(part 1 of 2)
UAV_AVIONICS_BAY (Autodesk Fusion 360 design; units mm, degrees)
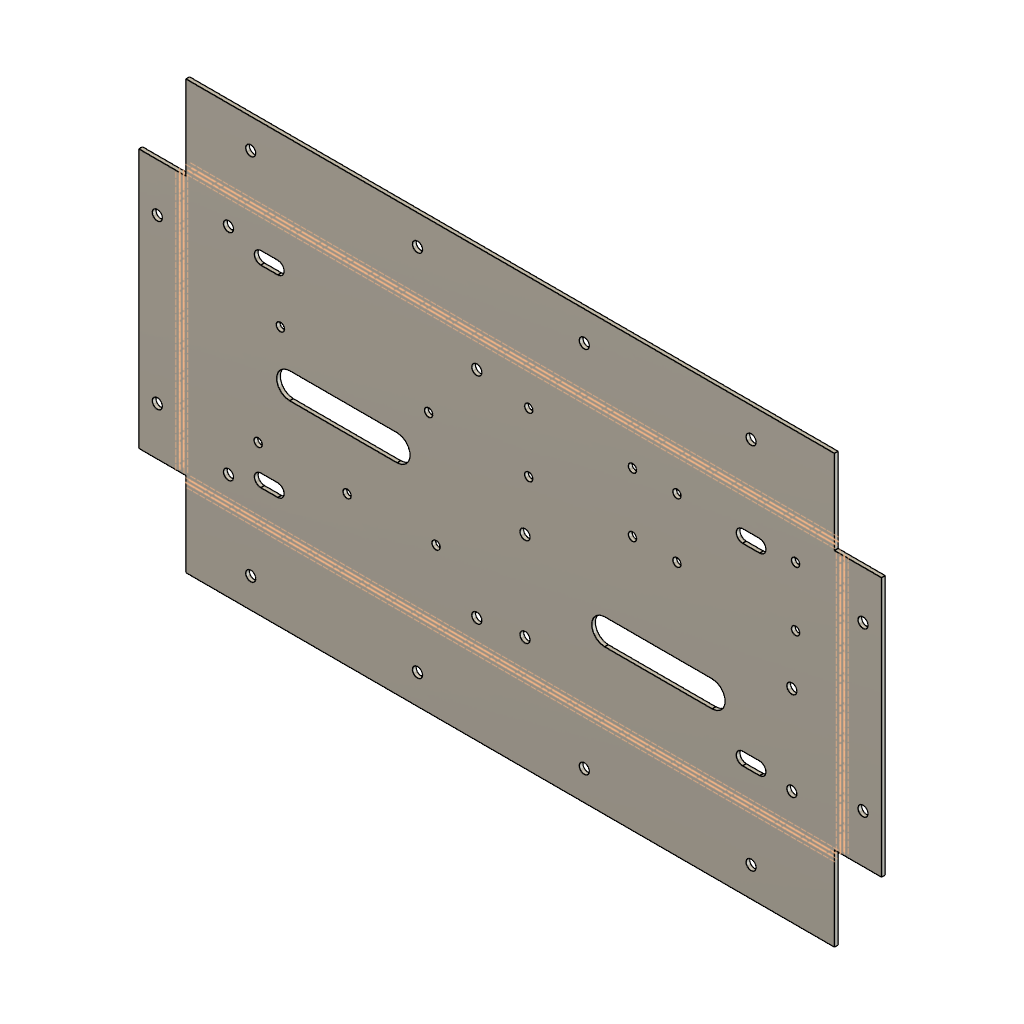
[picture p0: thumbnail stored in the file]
part number: 2026-11-24-01-47-07-089
part number: 2026-11-24-01-47-07-310
part number: 2026-11-24-01-47-07-319
part number: 2026-11-24-01-47-07-329
part number: 2026-11-24-01-47-07-338
part number: 2026-11-24-01-47-07-347
part number: 2026-11-24-01-47-07-356
part number: 2026-11-24-01-47-07-365
part number: 2026-11-24-01-47-07-376
part number: 2026-11-24-01-47-07-425
part number: 2026-11-24-01-47-08-424
part number: 2026-11-24-01-47-08-869
part number: 2026-11-24-01-47-09-436
part number: 2026-11-24-01-47-10-412
part number: 2026-11-24-01-47-11-202
part number: 2026-11-24-01-47-12-345
part number: 2026-11-24-01-47-13-053
part number: 2026-11-24-01-47-13-521
part number: 2026-11-24-01-47-15-030
part number: 2026-11-24-01-47-16-670
parameter "BAY_LENGTH" = 180 comment "[Assumption] Concept avionics bay overall outer length (X)"
parameter "BAY_WIDTH" = 75 comment "[Assumption] Concept avionics bay overall outer width (Y)"
parameter "BAY_HEIGHT" = 45 comment "[Assumption] Concept avionics bay overall outer height (Z)"
parameter "TRAY_FLANGE_H" = 22 comment "[Preliminary] Base tray perimeter upward flange height"
parameter "COVER_SKIRT_H" = 10 comment "[Preliminary] Top cover downward perimeter skirt height"
parameter "FORWARD_ZONE_END_X" = 94 comment "[Preliminary] X-boundary separating battery zone and aft deck"
parameter "HATCH_LENGTH" = 84 comment "[Preliminary] Service access hatch opening length"
parameter "HATCH_WIDTH" = 49 comment "[Preliminary] Service access hatch opening width"
parameter "T_BASE_TRAY" = 1 comment "[Preliminary] Main folded base tray thickness"
parameter "T_TOP_COVER" = 0.8 comment "[Preliminary] Removable top cover thickness"
parameter "T_ACCESS_HATCH" = 0.8 comment "[Preliminary] Service access hatch thickness"
parameter "T_SIDE_RAIL" = 1 comment "[Preliminary] Left and right side support rails thickness"
parameter "T_BULKHEAD" = 1 comment "[Preliminary] Front, rear, and connector bulkheads thickness"
parameter "T_EQUIP_DECK" = 1 comment "[Preliminary] Removable internal equipment deck thickness"
parameter "T_BRACKET" = 1 comment "[Preliminary] Structural and retention brackets thickness"
parameter "T_CABLE_CH" = 0.8 comment "[Preliminary] Cable routing channel and clamp thickness"
parameter "BEND_R_1_0" = 1 comment "[Preliminary] Inside bend radius for 1.0 mm Al 5052-H32"
parameter "BEND_R_0_8" = 0.8 comment "[Preliminary] Inside bend radius for 0.8 mm Al 5052-H32"
parameter "RELIEF_W_1_0" = 1.5 comment "[Preliminary] Bend relief width for 1.0 mm sheet"
parameter "RELIEF_D_1_0" = 2.5 comment "[Preliminary] Bend relief depth for 1.0 mm sheet"
parameter "RELIEF_W_0_8" = 1.2 comment "[Preliminary] Bend relief width for 0.8 mm sheet"
parameter "RELIEF_D_0_8" = 2.1 comment "[Preliminary] Bend relief depth for 0.8 mm sheet"
parameter "HOLE_CLR_M2_0" = 2.2 comment "[Preliminary] M2.0 medium clearance hole diameter"
parameter "HOLE_CLR_M2_5" = 2.7 comment "[Preliminary] M2.5 medium clearance hole diameter"
parameter "HOLE_CLR_M3_0" = 3.4 comment "[Preliminary] M3.0 medium clearance hole diameter"
parameter "HEAD_DIA_M2_0" = 3.8 comment "[Preliminary] ISO 4762/7380 M2.0 head diameter"
parameter "HEAD_DIA_M2_5" = 4.5 comment "[Preliminary] ISO 4762/7380 M2.5 head diameter"
parameter "STANDOFF_DECK_H" = 6 comment "[Preliminary] Under-deck plenum standoff height"
parameter "STANDOFF_PCB_H" = 4 comment "[Preliminary] PCB mounting standoff height"
parameter "ISO_PAD_THICK" = 2 comment "[Preliminary] Battery elastomer isolation pad thickness"
parameter "CLR_EQUIP_WALL" = 2 comment "[Preliminary] Minimum clearance between electronics and walls"
parameter "CLR_COMPONENT" = 1.5 comment "[Preliminary] General minimum clearance between adjacent parts"
parameter "CLR_SLIP_FIT" = 0.25 comment "[Preliminary] Per-side slip clearance for nested sheet metal parts"
parameter "CLR_COVER_FIT" = 0.3 comment "[Preliminary] Per-side clearance between cover skirt and chassis"
parameter "CLR_HATCH_GAP" = 0.5 comment "[Preliminary] Perimeter gap around removable service hatch"
parameter "d37" = 2
parameter "d38" = 1
parameter "d39" = 0.8
place_component sketch "SK_PCB_Substrate"
place_component sketch "SK_PCB_Substrate"
place_component sketch "SK_PCB_Substrate"
place_component sketch "SK_PCB_Substrate"
place_component sketch "SK_PCB_Substrate"
place_component sketch "SK_PCB_Substrate"
place_component sketch "SK_PCB_Substrate"
place_component sketch "SK_PCB_Substrate"
place_component sketch "SK_PCB_Substrate"
sketch "SK_Base_Tray_Blank" plane through (0, 0, 0) normal (0, 0, 1) x axis (1, 0, 0)
  line L1 (177.5, -37.5) -> (2.5, -37.5)
  line L2 (177.5, -35) -> (177.5, -37.5)
  line L3 (180, -35) -> (177.5, -35)
  line L4 (180, 35) -> (180, -35)
  line L5 (177.5, 35) -> (180, 35)
  line L6 (177.5, 37.5) -> (177.5, 35)
  line L7 (2.5, 37.5) -> (177.5, 37.5)
  line L8 (2.5, 35) -> (2.5, 37.5)
  line L9 (0, 35) -> (2.5, 35)
  line L10 (0, -35) -> (0, 35)
  line L11 (2.5, -35) -> (0, -35)
  line L12 (2.5, -37.5) -> (2.5, -35)
face "BaseFlange1" sketch "SK_Base_Tray_Blank"
face "EdgeFlange2" FlangeHeight 22 FlangeAngle 90
face "EdgeFlange3" FlangeHeight 12 FlangeAngle 90
sketch "SK_Base_Tray_Floor_Cutouts" plane through (0, 0, 0) normal (0, 0, 1) x axis (1, 0, 0)
  line L1 (27.3, -24.3) -> (22.7, -24.3)
  line L2 (22.7, -27.7) -> (27.3, -27.7)
  line L3 (27.3, 27.7) -> (22.7, 27.7)
  line L4 (22.7, 24.3) -> (27.3, 24.3)
  line L5 (157.3, -24.3) -> (152.7, -24.3)
  line L6 (152.7, -27.7) -> (157.3, -27.7)
  line L7 (157.3, 27.7) -> (152.7, 27.7)
  line L8 (152.7, 24.3) -> (157.3, 24.3)
  line L9 (64.5, -11.5) -> (35.5, -11.5)
  line L10 (35.5, -18.5) -> (64.5, -18.5)
  line L11 (149.5, 3.5) -> (120.5, 3.5)
  line L12 (120.5, -3.5) -> (149.5, -3.5)
  arc A1 centre (27.3, -26) radius 1.7 clockwise from (27.3, -24.3) to (27.3, -27.7)
  arc A2 centre (22.7, -26) radius 1.7 clockwise from (22.7, -27.7) to (22.7, -24.3)
  arc A3 centre (27.3, 26) radius 1.7 clockwise from (27.3, 27.7) to (27.3, 24.3)
  arc A4 centre (22.7, 26) radius 1.7 clockwise from (22.7, 24.3) to (22.7, 27.7)
  arc A5 centre (157.3, -26) radius 1.7 clockwise from (157.3, -24.3) to (157.3, -27.7)
  arc A6 centre (152.7, -26) radius 1.7 clockwise from (152.7, -27.7) to (152.7, -24.3)
  arc A7 centre (157.3, 26) radius 1.7 clockwise from (157.3, 27.7) to (157.3, 24.3)
  arc A8 centre (152.7, 26) radius 1.7 clockwise from (152.7, 24.3) to (152.7, 27.7)
  circle C1 centre (99, -29) radius 1.35
  circle C2 centre (99, 29) radius 1.35
  circle C3 centre (166, -29) radius 1.35
  circle C4 centre (166, 29) radius 1.35
  circle C5 centre (14, -27) radius 1.35
  circle C6 centre (14, -3) radius 1.35
  circle C7 centre (86, -27) radius 1.35
  circle C8 centre (86, -3) radius 1.35
  circle C9 centre (112, 12.5) radius 1.1
  circle C10 centre (152, 12.5) radius 1.1
  circle C11 centre (110, -17.5) radius 1.1
  circle C12 centre (134, -17.5) radius 1.1
  circle C13 centre (158, -17.5) radius 1.1
  circle C14 centre (13, 11) radius 1.1
  circle C15 centre (13, 27) radius 1.1
  circle C16 centre (45, 11) radius 1.1
  circle C17 centre (45, 27) radius 1.1
  circle C18 centre (57, 11) radius 1.1
  circle C19 centre (57, 27) radius 1.1
  circle C20 centre (85, 11) radius 1.1
  circle C21 centre (85, 27) radius 1.1
  arc A9 centre (64.5, -15) radius 3.5 clockwise from (64.5, -11.5) to (64.5, -18.5)
  arc A10 centre (35.5, -15) radius 3.5 clockwise from (35.5, -18.5) to (35.5, -11.5)
  arc A11 centre (149.5, 0) radius 3.5 clockwise from (149.5, 3.5) to (149.5, -3.5)
  arc A12 centre (120.5, 0) radius 3.5 clockwise from (120.5, -3.5) to (120.5, 3.5)
extrude "Extrude1" cut sketch "SK_Base_Tray_Floor_Cutouts" distance 2
work_plane "WorkPlane1" AlongDistance -37.5 ExtraOffset 0
sketch "SK_Tray_Left_Wall_Holes" plane through (0, -37.5, 0) normal (0, 1, 0) x axis (1, 0, 0)
  circle C1 centre (25, -14) radius 1.35
  circle C2 centre (70, -14) radius 1.35
  circle C3 centre (115, -14) radius 1.35
  circle C4 centre (160, -14) radius 1.35
extrude "Extrude2" cut sketch "SK_Tray_Left_Wall_Holes" distance 2
work_plane "WorkPlane2" AlongDistance 37.5 ExtraOffset 0
sketch "SK_Tray_Right_Wall_Holes" plane through (0, 37.5, 0) normal (0, 1, 0) x axis (1, 0, 0)
  circle C1 centre (25, -14) radius 1.35
  circle C2 centre (70, -14) radius 1.35
  circle C3 centre (115, -14) radius 1.35
  circle C4 centre (160, -14) radius 1.35
extrude "Extrude3" cut sketch "SK_Tray_Right_Wall_Holes" distance 2
sketch "SK_Tray_Front_Lip_Holes" plane through (0, 0, 0) normal (1, 0, 0) x axis (0, 0, -1)
  circle C1 centre (-7, -22) radius 1.35
  circle C2 centre (-7, 22) radius 1.35
extrude "Extrude4" cut sketch "SK_Tray_Front_Lip_Holes" distance 2
work_plane "WorkPlane3" AlongDistance 180 ExtraOffset 0
sketch "SK_Tray_Rear_Lip_Holes" plane through (180, 0, 0) normal (1, 0, 0) x axis (0, 0, -1)
  circle C1 centre (-7, -22) radius 1.35
  circle C2 centre (-7, 22) radius 1.35
extrude "Extrude5" cut sketch "SK_Tray_Rear_Lip_Holes" distance 2
place_component sketch "SK_PCB_Substrate"
work_plane "WorkPlane1" AlongDistance -36.35 ExtraOffset 0
sketch "SK_PDB-01-102_Left_Side_Rail_Web" plane through (0, -36.35, 0) normal (0, 1, 0) x axis (1, 0, 0)
  line L1 (177, -7) -> (3, -7)
  line L2 (177, -44) -> (177, -7)
  line L3 (3, -44) -> (177, -44)
  line L4 (3, -7) -> (3, -44)
face "BaseFlange1" sketch "SK_PDB-01-102_Left_Side_Rail_Web"
face "EdgeFlange2" FlangeHeight 9 FlangeAngle 90
sketch "SK_PDB-01-102_Left_Side_Rail_Web_Features" plane through (0, -36.35, 0) normal (0, 1, 0) x axis (1, 0, 0)
  line L1 (57.25, -34.25) -> (37.75, -34.25)
  line L2 (37.75, -27.75) -> (57.25, -27.75)
  line L3 (102.25, -34.25) -> (82.75, -34.25)
  line L4 (82.75, -27.75) -> (102.25, -27.75)
  line L5 (147.25, -34.25) -> (127.75, -34.25)
  line L6 (127.75, -27.75) -> (147.25, -27.75)
  circle C1 centre (25, -14) radius 1.35
  circle C2 centre (70, -14) radius 1.35
  circle C3 centre (115, -14) radius 1.35
  circle C4 centre (160, -14) radius 1.35
  circle C5 centre (7, -28) radius 1.35
  circle C6 centre (173, -28) radius 1.35
  arc A1 centre (57.25, -31) radius 3.25 clockwise from (57.25, -27.75) to (57.25, -34.25)
  arc A2 centre (37.75, -31) radius 3.25 clockwise from (37.75, -34.25) to (37.75, -27.75)
  arc A3 centre (102.25, -31) radius 3.25 clockwise from (102.25, -27.75) to (102.25, -34.25)
  arc A4 centre (82.75, -31) radius 3.25 clockwise from (82.75, -34.25) to (82.75, -27.75)
  arc A5 centre (147.25, -31) radius 3.25 clockwise from (147.25, -27.75) to (147.25, -34.25)
  arc A6 centre (127.75, -31) radius 3.25 clockwise from (127.75, -34.25) to (127.75, -27.75)
extrude "Extrude1" cut sketch "SK_PDB-01-102_Left_Side_Rail_Web_Features" distance 2
work_plane "WorkPlane2" AlongDistance 44 ExtraOffset 0
sketch "SK_PDB-01-102_Left_Side_Rail_Top_Holes" plane through (0, 0, 44) normal (0, 0, 1) x axis (1, 0, 0)
  circle C1 centre (25, -31.5) radius 1.35
  circle C2 centre (70, -31.5) radius 1.35
  circle C3 centre (115, -31.5) radius 1.35
  circle C4 centre (160, -31.5) radius 1.35
extrude "Extrude2" cut sketch "SK_PDB-01-102_Left_Side_Rail_Top_Holes" distance 2
place_component sketch "SK_PCB_Substrate"
work_plane "WorkPlane1" AlongDistance 36.35 ExtraOffset 0
sketch "SK_PDB-01-103_Right_Side_Rail_Web" plane through (0, 36.35, 0) normal (0, 1, 0) x axis (1, 0, 0)
  line L1 (177, -7) -> (3, -7)
  line L2 (177, -44) -> (177, -7)
  line L3 (3, -44) -> (177, -44)
  line L4 (3, -7) -> (3, -44)
face "BaseFlange2" sketch "SK_PDB-01-103_Right_Side_Rail_Web"
face "EdgeFlange3" FlangeHeight 9 FlangeAngle 90
sketch "SK_PDB-01-103_Right_Side_Rail_Web_Features" plane through (0, 36.35, 0) normal (0, 1, 0) x axis (1, 0, 0)
  line L1 (57.25, -34.25) -> (37.75, -34.25)
  line L2 (37.75, -27.75) -> (57.25, -27.75)
  line L3 (102.25, -34.25) -> (82.75, -34.25)
  line L4 (82.75, -27.75) -> (102.25, -27.75)
  line L5 (147.25, -34.25) -> (127.75, -34.25)
  line L6 (127.75, -27.75) -> (147.25, -27.75)
  circle C1 centre (25, -14) radius 1.35
  circle C2 centre (70, -14) radius 1.35
  circle C3 centre (115, -14) radius 1.35
  circle C4 centre (160, -14) radius 1.35
  circle C5 centre (7, -28) radius 1.35
  circle C6 centre (173, -28) radius 1.35
  arc A1 centre (57.25, -31) radius 3.25 clockwise from (57.25, -27.75) to (57.25, -34.25)
  arc A2 centre (37.75, -31) radius 3.25 clockwise from (37.75, -34.25) to (37.75, -27.75)
  arc A3 centre (102.25, -31) radius 3.25 clockwise from (102.25, -27.75) to (102.25, -34.25)
  arc A4 centre (82.75, -31) radius 3.25 clockwise from (82.75, -34.25) to (82.75, -27.75)
  arc A5 centre (147.25, -31) radius 3.25 clockwise from (147.25, -27.75) to (147.25, -34.25)
  arc A6 centre (127.75, -31) radius 3.25 clockwise from (127.75, -34.25) to (127.75, -27.75)
extrude "Extrude1" cut sketch "SK_PDB-01-103_Right_Side_Rail_Web_Features" distance 2
work_plane "WorkPlane2" AlongDistance 44 ExtraOffset 0
sketch "SK_PDB-01-103_Right_Side_Rail_Top_Holes" plane through (0, 0, 44) normal (0, 0, 1) x axis (1, 0, 0)
  circle C1 centre (25, 31.5) radius 1.35
  circle C2 centre (70, 31.5) radius 1.35
  circle C3 centre (115, 31.5) radius 1.35
  circle C4 centre (160, 31.5) radius 1.35
extrude "Extrude2" cut sketch "SK_PDB-01-103_Right_Side_Rail_Top_Holes" distance 2
place_component sketch "SK_PCB_Substrate"
work_plane "WorkPlane1" AlongDistance 1.15 ExtraOffset 0
sketch "SK_Front_Bulkhead_Blank" plane through (1.15, 0, 0) normal (1, 0, 0) x axis (0, 0, -1)
  line L1 (-2.5, 35.2) -> (-2.5, -35.2)
  line L2 (-39.8, 35.2) -> (-2.5, 35.2)
  line L3 (-39.8, 32.2) -> (-39.8, 35.2)
  line L4 (-42.8, 32.2) -> (-39.8, 32.2)
  line L5 (-42.8, -32.2) -> (-42.8, 32.2)
  line L6 (-39.8, -32.2) -> (-42.8, -32.2)
  line L7 (-39.8, -35.2) -> (-39.8, -32.2)
  line L8 (-2.5, -35.2) -> (-39.8, -35.2)
face "BaseFlange1" sketch "SK_Front_Bulkhead_Blank"
face "EdgeFlange2" FlangeHeight 10 FlangeAngle 90
face "EdgeFlange3" FlangeHeight 8 FlangeAngle 90
sketch "SK_Front_Bulkhead_Cutouts" plane through (1.15, 0, 0) normal (1, 0, 0) x axis (0, 0, -1)
  line L1 (-26.5, -16.5) -> (-26.5, -23.5)
  line L2 (-21.5, -23.5) -> (-21.5, -16.5)
  line L3 (-26.5, 23.5) -> (-26.5, 16.5)
  line L4 (-21.5, 16.5) -> (-21.5, 23.5)
  circle C1 centre (-7, -22) radius 1.35
  circle C2 centre (-7, 22) radius 1.35
  circle C3 centre (-24, 0) radius 5
  circle C4 centre (-24, -9) radius 1.1
  circle C5 centre (-24, 9) radius 1.1
  arc A1 centre (-24, -16.5) radius 2.5 clockwise from (-26.5, -16.5) to (-21.5, -16.5)
  arc A2 centre (-24, -23.5) radius 2.5 clockwise from (-21.5, -23.5) to (-26.5, -23.5)
  arc A3 centre (-24, 23.5) radius 2.5 clockwise from (-26.5, 23.5) to (-21.5, 23.5)
  arc A4 centre (-24, 16.5) radius 2.5 clockwise from (-21.5, 16.5) to (-26.5, 16.5)
extrude "Extrude1" cut sketch "SK_Front_Bulkhead_Cutouts" distance 2
work_plane "WorkPlane2" AlongDistance -35.2 ExtraOffset 0
sketch "SK_Front_Left_Hole" plane through (0, -35.2, 0) normal (0, 1, 0) x axis (1, 0, 0)
  circle C1 centre (7, -28) radius 1.35
extrude "Extrude2" cut sketch "SK_Front_Left_Hole" distance 2
work_plane "WorkPlane3" AlongDistance 35.2 ExtraOffset 0
sketch "SK_Front_Right_Hole" plane through (0, 35.2, 0) normal (0, 1, 0) x axis (1, 0, 0)
  circle C1 centre (7, -28) radius 1.35
extrude "Extrude3" cut sketch "SK_Front_Right_Hole" distance 2
place_component sketch "SK_PCB_Substrate"
work_plane "WorkPlane1" AlongDistance 178.85 ExtraOffset 0
sketch "SK_Rear_Bulkhead_Blank" plane through (178.85, 0, 0) normal (1, 0, 0) x axis (0, 0, -1)
  line L1 (-2.5, 35.2) -> (-2.5, -35.2)
  line L2 (-39.8, 35.2) -> (-2.5, 35.2)
  line L3 (-39.8, 32.2) -> (-39.8, 35.2)
  line L4 (-42.8, 32.2) -> (-39.8, 32.2)
  line L5 (-42.8, -32.2) -> (-42.8, 32.2)
  line L6 (-39.8, -32.2) -> (-42.8, -32.2)
  line L7 (-39.8, -35.2) -> (-39.8, -32.2)
  line L8 (-2.5, -35.2) -> (-39.8, -35.2)
face "BaseFlange2" sketch "SK_Rear_Bulkhead_Blank"
face "EdgeFlange3" FlangeHeight 10 FlangeAngle 90
face "EdgeFlange4" FlangeHeight 8 FlangeAngle 90
sketch "SK_Rear_Bulkhead_Cutouts" plane through (178.85, 0, 0) normal (1, 0, 0) x axis (0, 0, -1)
  line L1 (-16, 24) -> (-16, -24)
  line L2 (-36, 24) -> (-16, 24)
  line L3 (-36, -24) -> (-36, 24)
  line L4 (-16, -24) -> (-36, -24)
  circle C1 centre (-7, -22) radius 1.35
  circle C2 centre (-7, 22) radius 1.35
  circle C3 centre (-18, -28.5) radius 1.1
  circle C4 centre (-34, -28.5) radius 1.1
  circle C5 centre (-18, 28.5) radius 1.1
  circle C6 centre (-34, 28.5) radius 1.1
extrude "Extrude1" cut sketch "SK_Rear_Bulkhead_Cutouts" distance 2
work_plane "WorkPlane2" AlongDistance -35.2 ExtraOffset 0
sketch "SK_Rear_Left_Hole" plane through (0, -35.2, 0) normal (0, 1, 0) x axis (1, 0, 0)
  circle C1 centre (173, -28) radius 1.35
extrude "Extrude2" cut sketch "SK_Rear_Left_Hole" distance 2
work_plane "WorkPlane3" AlongDistance 35.2 ExtraOffset 0
sketch "SK_Rear_Right_Hole" plane through (0, 35.2, 0) normal (0, 1, 0) x axis (1, 0, 0)
  circle C1 centre (173, -28) radius 1.35
extrude "Extrude3" cut sketch "SK_Rear_Right_Hole" distance 2
place_component sketch "SK_PCB_Substrate"
work_plane "WorkPlane1" AlongDistance 45 ExtraOffset 0
sketch "SK_Top_Cover_Blank" plane through (0, 0, 45) normal (0, 0, 1) x axis (1, 0, 0)
  line L1 (177.8, -37.5) -> (2.2, -37.5)
  line L2 (177.8, -35.3) -> (177.8, -37.5)
  line L3 (180, -35.3) -> (177.8, -35.3)
  line L4 (180, 35.3) -> (180, -35.3)
  line L5 (177.8, 35.3) -> (180, 35.3)
  line L6 (177.8, 37.5) -> (177.8, 35.3)
  line L7 (2.2, 37.5) -> (177.8, 37.5)
  line L8 (2.2, 35.3) -> (2.2, 37.5)
  line L9 (0, 35.3) -> (2.2, 35.3)
  line L10 (0, -35.3) -> (0, 35.3)
  line L11 (2.2, -35.3) -> (0, -35.3)
  line L12 (2.2, -37.5) -> (2.2, -35.3)
face "BaseFlange2" sketch "SK_Top_Cover_Blank"
face "EdgeFlange3" FlangeHeight 10 FlangeAngle 90
face "EdgeFlange4" FlangeHeight 10 FlangeAngle 90
sketch "SK_Top_Cover_Cutouts" plane through (0, 0, 45) normal (0, 0, 1) x axis (1, 0, 0)
  line L1 (94, -24.5) -> (10, -24.5)
  line L2 (94, 24.5) -> (94, -24.5)
  line L3 (10, 24.5) -> (94, 24.5)
  line L4 (10, -24.5) -> (10, 24.5)
  line L5 (114, 16) -> (114, -16)
  line L6 (110, -16) -> (110, 16)
  line L7 (124, 16) -> (124, -16)
  line L8 (120, -16) -> (120, 16)
  line L9 (134, 16) -> (134, -16)
  line L10 (130, -16) -> (130, 16)
  line L11 (144, 16) -> (144, -16)
  line L12 (140, -16) -> (140, 16)
  line L13 (154, 16) -> (154, -16)
  line L14 (150, -16) -> (150, 16)
  line L15 (164, 16) -> (164, -16)
  line L16 (160, -16) -> (160, 16)
  circle C1 centre (25, -31.5) radius 1.35
  circle C2 centre (25, 31.5) radius 1.35
  circle C3 centre (70, -31.5) radius 1.35
  circle C4 centre (70, 31.5) radius 1.35
  circle C5 centre (115, -31.5) radius 1.35
  circle C6 centre (115, 31.5) radius 1.35
  circle C7 centre (160, -31.5) radius 1.35
  circle C8 centre (160, 31.5) radius 1.35
  circle C9 centre (6.5, -13) radius 1.1
  circle C10 centre (6.5, 13) radius 1.1
  circle C11 centre (97.5, -13) radius 1.1
  circle C12 centre (97.5, 13) radius 1.1
  arc A1 centre (112, 16) radius 2 clockwise from (110, 16) to (114, 16)
  arc A2 centre (112, -16) radius 2 clockwise from (114, -16) to (110, -16)
  arc A3 centre (122, 16) radius 2 clockwise from (120, 16) to (124, 16)
  arc A4 centre (122, -16) radius 2 clockwise from (124, -16) to (120, -16)
  arc A5 centre (132, 16) radius 2 clockwise from (130, 16) to (134, 16)
  arc A6 centre (132, -16) radius 2 clockwise from (134, -16) to (130, -16)
  arc A7 centre (142, 16) radius 2 clockwise from (140, 16) to (144, 16)
  arc A8 centre (142, -16) radius 2 clockwise from (144, -16) to (140, -16)
  arc A9 centre (152, 16) radius 2 clockwise from (150, 16) to (154, 16)
  arc A10 centre (152, -16) radius 2 clockwise from (154, -16) to (150, -16)
  arc A11 centre (162, 16) radius 2 clockwise from (160, 16) to (164, 16)
  arc A12 centre (162, -16) radius 2 clockwise from (164, -16) to (160, -16)
extrude "Extrude1" cut sketch "SK_Top_Cover_Cutouts" distance 2
place_component sketch "SK_PCB_Substrate"
work_plane "WorkPlane1" AlongDistance 45 ExtraOffset 0
sketch "SK_Access_Hatch_Blank" plane through (0, 0, 45) normal (0, 0, 1) x axis (1, 0, 0)
  line L1 (93.5, -24) -> (10.5, -24)
  line L2 (93.5, 24) -> (93.5, -24)
  line L3 (10.5, 24) -> (93.5, 24)
  line L4 (10.5, -24) -> (10.5, 24)
face "BaseFlange2" sketch "SK_Access_Hatch_Blank"
face "Hem3" HemGap 0.02 HemLength 4.5
face "Hem4" HemGap 0.02 HemLength 4.5
sketch "SK_Access_Hatch_Cutouts" plane through (0, 0, 45) normal (0, 0, 1) x axis (1, 0, 0)
  line L1 (37.75, 10.25) -> (37.75, -10.25)
  line L2 (34.25, -10.25) -> (34.25, 10.25)
  line L3 (49.75, 10.25) -> (49.75, -10.25)
  line L4 (46.25, -10.25) -> (46.25, 10.25)
  line L5 (61.75, 10.25) -> (61.75, -10.25)
  line L6 (58.25, -10.25) -> (58.25, 10.25)
  line L7 (78.5, 4.5) -> (78.5, -4.5)
  line L8 (73.5, -4.5) -> (73.5, 4.5)
  circle C1 centre (14.5, -13) radius 1.1
  circle C2 centre (14.5, 13) radius 1.1
  circle C3 centre (89.5, -13) radius 1.1
  circle C4 centre (89.5, 13) radius 1.1
  arc A1 centre (36, 10.25) radius 1.75 clockwise from (34.25, 10.25) to (37.75, 10.25)
  arc A2 centre (36, -10.25) radius 1.75 clockwise from (37.75, -10.25) to (34.25, -10.25)
  arc A3 centre (48, 10.25) radius 1.75 clockwise from (46.25, 10.25) to (49.75, 10.25)
  arc A4 centre (48, -10.25) radius 1.75 clockwise from (49.75, -10.25) to (46.25, -10.25)
  arc A5 centre (60, 10.25) radius 1.75 clockwise from (58.25, 10.25) to (61.75, 10.25)
  arc A6 centre (60, -10.25) radius 1.75 clockwise from (61.75, -10.25) to (58.25, -10.25)
  arc A7 centre (76, 4.5) radius 2.5 clockwise from (73.5, 4.5) to (78.5, 4.5)
  arc A8 centre (76, -4.5) radius 2.5 clockwise from (78.5, -4.5) to (73.5, -4.5)
extrude "Extrude1" cut sketch "SK_Access_Hatch_Cutouts" distance 2
place_component sketch "SK_PCB_Substrate"
work_plane "WorkPlane1" AlongDistance 44.2 ExtraOffset 0
sketch "SK_Retainer_Strip_Blank" plane through (0, 0, 44.2) normal (0, 0, 1) x axis (1, 0, 0)
  line L1 (18, -18) -> (3, -18)
  line L2 (18, 18) -> (18, -18)
  line L3 (3, 18) -> (18, 18)
  line L4 (3, -18) -> (3, 18)
face "BaseFlange2" sketch "SK_Retainer_Strip_Blank"
sketch "SK_Retainer_Strip_Holes" plane through (0, 0, 44.2) normal (0, 0, 1) x axis (1, 0, 0)
  circle C1 centre (6.5, -13) radius 1.1
  circle C2 centre (6.5, 13) radius 1.1
  circle C3 centre (14.5, -13) radius 1.1
  circle C4 centre (14.5, 13) radius 1.1
extrude "Extrude1" cut sketch "SK_Retainer_Strip_Holes" distance 2
copy_paste "CopyPaste1"
place_component sketch "SK_PCB_Substrate"
work_plane "WorkPlane1" AlongDistance 7 ExtraOffset 0
sketch "SK_Equipment_Deck_Blank" plane through (0, 0, 7) normal (0, 0, 1) x axis (1, 0, 0)
  line L1 (174, -33.5) -> (94, -33.5)
  line L2 (174, 33.5) -> (174, -33.5)
  line L3 (94, 33.5) -> (174, 33.5)
  line L4 (94, -33.5) -> (94, 33.5)
face "BaseFlange1" sketch "SK_Equipment_Deck_Blank"
face "EdgeFlange2" FlangeHeight 6 FlangeAngle 90
sketch "SK_Equipment_Deck_Cutouts" plane through (0, 0, 7) normal (0, 0, 1) x axis (1, 0, 0)
  line L1 (131.5, -10) -> (115.5, -10)
  line L2 (115.5, -16) -> (131.5, -16)
  line L3 (144.75, 23) -> (144.75, 11)
  line L4 (140.75, 11) -> (140.75, 23)
  circle C1 centre (99, -29) radius 1.35
  circle C2 centre (99, 29) radius 1.35
  circle C3 centre (166, -29) radius 1.35
  circle C4 centre (166, 29) radius 1.35
  circle C5 centre (106, -28) radius 1.1
  circle C6 centre (106, 2) radius 1.1
  circle C7 centre (141, -28) radius 1.1
  circle C8 centre (141, 2) radius 1.1
  circle C9 centre (105.5, 12) radius 1.1
  circle C10 centre (105.5, 28) radius 1.1
  circle C11 centre (135.5, 12) radius 1.1
  circle C12 centre (135.5, 28) radius 1.1
  circle C13 centre (150, -22) radius 1.1
  circle C14 centre (150, -4) radius 1.1
  circle C15 centre (168, -22) radius 1.1
  circle C16 centre (168, -4) radius 1.1
  circle C17 centre (150, 5) radius 1.1
  circle C18 centre (150, 23) radius 1.1
  circle C19 centre (168, 5) radius 1.1
  circle C20 centre (168, 23) radius 1.1
  arc A1 centre (131.5, -13) radius 3 clockwise from (131.5, -10) to (131.5, -16)
  arc A2 centre (115.5, -13) radius 3 clockwise from (115.5, -16) to (115.5, -10)
  arc A3 centre (142.75, 23) radius 2 clockwise from (140.75, 23) to (144.75, 23)
  arc A4 centre (142.75, 11) radius 2 clockwise from (144.75, 11) to (140.75, 11)
extrude "Extrude1" cut sketch "SK_Equipment_Deck_Cutouts" distance 2
sketch "SK_PCB_Clamp_Blank" plane through (0, 0, 0) normal (0, 0, 1) x axis (1, 0, 0)
  line L1 (3, -17.5) -> (-4, -17.5)
  line L2 (3, 17.5) -> (3, -17.5)
  line L3 (-4, 17.5) -> (3, 17.5)
  line L4 (-4, -17.5) -> (-4, 17.5)
face "BaseFlange1" sketch "SK_PCB_Clamp_Blank"
face "EdgeFlange2" FlangeHeight 6 FlangeAngle 90
sketch "SK_PCB_Clamp_Holes" plane through (0, 0, 0) normal (0, 0, 1) x axis (1, 0, 0)
  circle C1 centre (0, -15) radius 1.1
  circle C2 centre (0, 15) radius 1.1
extrude "Extrude1" cut sketch "SK_PCB_Clamp_Holes" distance 2
copy_paste "CopyPaste1"
place_component sketch "SK_PDB-03-303_Deck_Standoff_M2_5x6_Body"
sketch "SK_PDB-03-303_Deck_Standoff_M2_5x6_Body" plane through (0, 0, 0) normal (0, 0, 1) x axis (1, 0, 0)
  circle C1 centre (0, 0) radius 2.5
  circle C2 centre (0, 0) radius 1.3
extrude "Extrude1" new body sketch "SK_PDB-03-303_Deck_Standoff_M2_5x6_Body" along normal blind 6
copy_paste "CopyPaste2"
copy_paste "CopyPaste3"
copy_paste "CopyPaste4"
place_component sketch "SK_PDB-03-304_PCB_Standoff_M2x4_Body"
sketch "SK_PDB-03-304_PCB_Standoff_M2x4_Body" plane through (0, 0, 0) normal (0, 0, 1) x axis (1, 0, 0)
  circle C1 centre (0, 0) radius 2
  circle C2 centre (0, 0) radius 1.05
extrude "Extrude1" new body sketch "SK_PDB-03-304_PCB_Standoff_M2x4_Body" along normal blind 4
copy_paste "CopyPaste5"
copy_paste "CopyPaste6"
copy_paste "CopyPaste7"
copy_paste "CopyPaste8"
copy_paste "CopyPaste9"
copy_paste "CopyPaste10"
copy_paste "CopyPaste11"
copy_paste "CopyPaste12"
copy_paste "CopyPaste13"
copy_paste "CopyPaste14"
copy_paste "CopyPaste15"
copy_paste "CopyPaste16"
copy_paste "CopyPaste17"
copy_paste "CopyPaste18"
copy_paste "CopyPaste19"
copy_paste "CopyPaste20"
copy_paste "CopyPaste21"
copy_paste "CopyPaste22"
copy_paste "CopyPaste23"
copy_paste "CopyPaste24"
copy_paste "CopyPaste25"
copy_paste "CopyPaste26"
copy_paste "CopyPaste27"
place_component sketch "SK_PCB_Substrate"
work_plane "WorkPlane1" AlongDistance 5 ExtraOffset 0
sketch "SK_PCB_Substrate" plane through (0, 0, 5) normal (0, 0, 1) x axis (1, 0, 0)
  line L1 (48, 8) -> (10, 8)
  line L2 (48, 30) -> (48, 8)
  line L3 (10, 30) -> (48, 30)
  line L4 (10, 8) -> (10, 30)
extrude "Extrude1" new body sketch "SK_PCB_Substrate" along normal blind 2
work_plane "WorkPlane2" AlongDistance 7 ExtraOffset 0
sketch "SK_Module_Housing" plane through (0, 0, 7) normal (0, 0, 1) x axis (1, 0, 0)
  line L1 (43, 13) -> (15, 13)
  line L2 (43, 25) -> (43, 13)
  line L3 (15, 25) -> (43, 25)
  line L4 (15, 13) -> (15, 25)
extrude "Extrude2" add sketch "SK_Module_Housing" along normal blind 8
work_plane "WorkPlane3" AlongDistance 5 ExtraOffset 0
sketch "SK_PCB_Mount_Holes" plane through (0, 0, 5) normal (0, 0, 1) x axis (1, 0, 0)
  circle C1 centre (13, 11) radius 1.1
  circle C2 centre (13, 27) radius 1.1
  circle C3 centre (45, 11) radius 1.1
  circle C4 centre (45, 27) radius 1.1
extrude "Extrude3" cut sketch "SK_PCB_Mount_Holes" distance 3
place_component sketch "SK_PCB_Substrate"
work_plane "WorkPlane1" AlongDistance 5 ExtraOffset 0
sketch "SK_PCB_Substrate" plane through (0, 0, 5) normal (0, 0, 1) x axis (1, 0, 0)
  line L1 (88, 8) -> (54, 8)
  line L2 (88, 30) -> (88, 8)
  line L3 (54, 30) -> (88, 30)
  line L4 (54, 8) -> (54, 30)
extrude "Extrude1" new body sketch "SK_PCB_Substrate" along normal blind 2
work_plane "WorkPlane2" AlongDistance 7 ExtraOffset 0
sketch "SK_Module_Housing" plane through (0, 0, 7) normal (0, 0, 1) x axis (1, 0, 0)
  line L1 (83, 13) -> (59, 13)
  line L2 (83, 25) -> (83, 13)
  line L3 (59, 25) -> (83, 25)
  line L4 (59, 13) -> (59, 25)
extrude "Extrude2" add sketch "SK_Module_Housing" along normal blind 8
work_plane "WorkPlane3" AlongDistance 5 ExtraOffset 0
sketch "SK_PCB_Mount_Holes" plane through (0, 0, 5) normal (0, 0, 1) x axis (1, 0, 0)
  circle C1 centre (57, 11) radius 1.1
  circle C2 centre (57, 27) radius 1.1
  circle C3 centre (85, 11) radius 1.1
  circle C4 centre (85, 27) radius 1.1
extrude "Extrude3" cut sketch "SK_PCB_Mount_Holes" distance 3
place_component sketch "SK_PCB_Substrate"
work_plane "WorkPlane1" AlongDistance 12 ExtraOffset 0
sketch "SK_PCB_Substrate" plane through (0, 0, 12) normal (0, 0, 1) x axis (1, 0, 0)
  line L1 (144.5, -31) -> (102.5, -31)
  line L2 (144.5, 5) -> (144.5, -31)
  line L3 (102.5, 5) -> (144.5, 5)
  line L4 (102.5, -31) -> (102.5, 5)
extrude "Extrude1" new body sketch "SK_PCB_Substrate" along normal blind 2
work_plane "WorkPlane2" AlongDistance 14 ExtraOffset 0
sketch "SK_Module_Housing" plane through (0, 0, 14) normal (0, 0, 1) x axis (1, 0, 0)
  line L1 (137.5, -26) -> (109.5, -26)
  line L2 (137.5, 0) -> (137.5, -26)
  line L3 (109.5, 0) -> (137.5, 0)
  line L4 (109.5, -26) -> (109.5, 0)
extrude "Extrude2" add sketch "SK_Module_Housing" along normal blind 10
work_plane "WorkPlane3" AlongDistance 12 ExtraOffset 0
sketch "SK_PCB_Mount_Holes" plane through (0, 0, 12) normal (0, 0, 1) x axis (1, 0, 0)
  circle C1 centre (106, -28) radius 1.1
  circle C2 centre (106, 2) radius 1.1
  circle C3 centre (141, -28) radius 1.1
  circle C4 centre (141, 2) radius 1.1
extrude "Extrude3" cut sketch "SK_PCB_Mount_Holes" distance 3
place_component sketch "SK_PCB_Substrate"
work_plane "WorkPlane1" AlongDistance 12 ExtraOffset 0
sketch "SK_PCB_Substrate" plane through (0, 0, 12) normal (0, 0, 1) x axis (1, 0, 0)
  line L1 (138.5, 9) -> (102.5, 9)
  line L2 (138.5, 31) -> (138.5, 9)
  line L3 (102.5, 31) -> (138.5, 31)
  line L4 (102.5, 9) -> (102.5, 31)
extrude "Extrude1" new body sketch "SK_PCB_Substrate" along normal blind 2
work_plane "WorkPlane2" AlongDistance 14 ExtraOffset 0
sketch "SK_Module_Housing" plane through (0, 0, 14) normal (0, 0, 1) x axis (1, 0, 0)
  line L1 (133.5, 14) -> (107.5, 14)
  line L2 (133.5, 26) -> (133.5, 14)
  line L3 (107.5, 26) -> (133.5, 26)
  line L4 (107.5, 14) -> (107.5, 26)
extrude "Extrude2" add sketch "SK_Module_Housing" along normal blind 8
work_plane "WorkPlane3" AlongDistance 12 ExtraOffset 0
sketch "SK_PCB_Mount_Holes" plane through (0, 0, 12) normal (0, 0, 1) x axis (1, 0, 0)
  circle C1 centre (105.5, 12) radius 1.1
  circle C2 centre (105.5, 28) radius 1.1
  circle C3 centre (135.5, 12) radius 1.1
  circle C4 centre (135.5, 28) radius 1.1
extrude "Extrude3" cut sketch "SK_PCB_Mount_Holes" distance 3
place_component sketch "SK_PCB_Substrate"
work_plane "WorkPlane1" AlongDistance 12 ExtraOffset 0
sketch "SK_PCB_Substrate" plane through (0, 0, 12) normal (0, 0, 1) x axis (1, 0, 0)
  line L1 (171, -25) -> (147, -25)
  line L2 (171, -1) -> (171, -25)
  line L3 (147, -1) -> (171, -1)
  line L4 (147, -25) -> (147, -1)
extrude "Extrude1" new body sketch "SK_PCB_Substrate" along normal blind 2
work_plane "WorkPlane2" AlongDistance 14 ExtraOffset 0
sketch "SK_Module_Housing" plane through (0, 0, 14) normal (0, 0, 1) x axis (1, 0, 0)
  line L1 (166, -20) -> (152, -20)
  line L2 (166, -6) -> (166, -20)
  line L3 (152, -6) -> (166, -6)
  line L4 (152, -20) -> (152, -6)
extrude "Extrude2" add sketch "SK_Module_Housing" along normal blind 7
work_plane "WorkPlane3" AlongDistance 12 ExtraOffset 0
sketch "SK_PCB_Mount_Holes" plane through (0, 0, 12) normal (0, 0, 1) x axis (1, 0, 0)
  circle C1 centre (150, -22) radius 1.1
  circle C2 centre (150, -4) radius 1.1
  circle C3 centre (168, -22) radius 1.1
  circle C4 centre (168, -4) radius 1.1
extrude "Extrude3" cut sketch "SK_PCB_Mount_Holes" distance 3
place_component sketch "SK_PCB_Substrate"
work_plane "WorkPlane1" AlongDistance 12 ExtraOffset 0
sketch "SK_PCB_Substrate" plane through (0, 0, 12) normal (0, 0, 1) x axis (1, 0, 0)
  line L1 (171, 2) -> (147, 2)
  line L2 (171, 26) -> (171, 2)
  line L3 (147, 26) -> (171, 26)
  line L4 (147, 2) -> (147, 26)
extrude "Extrude1" new body sketch "SK_PCB_Substrate" along normal blind 2
work_plane "WorkPlane2" AlongDistance 14 ExtraOffset 0
sketch "SK_Module_Housing" plane through (0, 0, 14) normal (0, 0, 1) x axis (1, 0, 0)
  line L1 (166, 7) -> (152, 7)
  line L2 (166, 21) -> (166, 7)
  line L3 (152, 21) -> (166, 21)
  line L4 (152, 7) -> (152, 21)
extrude "Extrude2" add sketch "SK_Module_Housing" along normal blind 6
work_plane "WorkPlane3" AlongDistance 12 ExtraOffset 0
sketch "SK_PCB_Mount_Holes" plane through (0, 0, 12) normal (0, 0, 1) x axis (1, 0, 0)
  circle C1 centre (150, 5) radius 1.1
  circle C2 centre (150, 23) radius 1.1
  circle C3 centre (168, 5) radius 1.1
  circle C4 centre (168, 23) radius 1.1
extrude "Extrude3" cut sketch "SK_PCB_Mount_Holes" distance 3
place_component sketch "SK_PCB_Substrate"
work_plane "WorkPlane1" AlongDistance 3 ExtraOffset 0
sketch "SK_Battery_Envelope_Solid" plane through (0, 0, 3) normal (0, 0, 1) x axis (1, 0, 0)
  line L1 (92, -32) -> (8, -32)
  line L2 (92, 2) -> (92, -32)
  line L3 (8, 2) -> (92, 2)
  line L4 (8, -32) -> (8, 2)
extrude "Extrude1" new body sketch "SK_Battery_Envelope_Solid" along normal blind 24
sketch "SK_Battery_Cradle_Blank" plane through (0, 0, 0) normal (0, 0, 1) x axis (1, 0, 0)
  line L1 (4, -18.2) -> (-4, -18.2)
  line L2 (4, 18.2) -> (4, -18.2)
  line L3 (-4, 18.2) -> (4, 18.2)
  line L4 (-4, -18.2) -> (-4, 18.2)
face "BaseFlange1" sketch "SK_Battery_Cradle_Blank"
face "EdgeFlange2" FlangeHeight 27 FlangeAngle 90
sketch "SK_Cradle_Floor_Holes" plane through (0, 0, 0) normal (0, 0, 1) x axis (1, 0, 0)
  circle C1 centre (0, -12) radius 1.35
  circle C2 centre (0, 12) radius 1.35
extrude "Extrude1" cut sketch "SK_Cradle_Floor_Holes" distance 2
work_plane "WorkPlane1" AlongDistance -18.2 ExtraOffset 0
sketch "SK_Cradle_Left_Slot" plane through (0, -18.2, 0) normal (0, 1, 0) x axis (1, 0, 0)
  line L1 (1.6, -19.9) -> (1.6, -9.1)
  line L2 (-1.6, -9.1) -> (-1.6, -19.9)
  arc A1 centre (0, -19.9) radius 1.6 clockwise from (1.6, -19.9) to (-1.6, -19.9)
  arc A2 centre (0, -9.1) radius 1.6 clockwise from (-1.6, -9.1) to (1.6, -9.1)
extrude "Extrude2" cut sketch "SK_Cradle_Left_Slot" distance 2
work_plane "WorkPlane2" AlongDistance 18.2 ExtraOffset 0
sketch "SK_Cradle_Right_Slot" plane through (0, 18.2, 0) normal (0, 1, 0) x axis (1, 0, 0)
  line L1 (1.6, -19.9) -> (1.6, -9.1)
  line L2 (-1.6, -9.1) -> (-1.6, -19.9)
  arc A1 centre (0, -19.9) radius 1.6 clockwise from (1.6, -19.9) to (-1.6, -19.9)
  arc A2 centre (0, -9.1) radius 1.6 clockwise from (-1.6, -9.1) to (1.6, -9.1)
extrude "Extrude3" cut sketch "SK_Cradle_Right_Slot" distance 2
copy_paste "CopyPaste1"
place_component sketch "SK_PCB_Substrate"
work_plane "WorkPlane1" AlongDistance 1 ExtraOffset 0
sketch "SK_Isolation_Pad_Body" plane through (0, 0, 1) normal (0, 0, 1) x axis (1, 0, 0)
  line L1 (81, -31) -> (19, -31)
  line L2 (81, 1) -> (81, -31)
  line L3 (19, 1) -> (81, 1)
  line L4 (19, -31) -> (19, 1)
extrude "Extrude1" new body sketch "SK_Isolation_Pad_Body" along normal blind 2
work_plane "WorkPlane2" AlongDistance 1 ExtraOffset 0
sketch "SK_Iso_Pad_Vent_Slot" plane through (0, 0, 1) normal (0, 0, 1) x axis (1, 0, 0)
  line L1 (64, -12) -> (36, -12)
  line L2 (36, -18) -> (64, -18)
  arc A1 centre (64, -15) radius 3 clockwise from (64, -12) to (64, -18)
  arc A2 centre (36, -15) radius 3 clockwise from (36, -18) to (36, -12)
extrude "Extrude2" cut sketch "SK_Iso_Pad_Vent_Slot" distance 3
work_plane "WorkPlane1" AlongDistance -2.5 ExtraOffset 0
sketch "SK_Retention_Strap_U" plane through (-2.5, 0, 0) normal (1, 0, 0) x axis (0, 0, -1)
  line L1 (-13.5, -18.3) -> (-13.5, -19.3)
  line L2 (-27.2, -18.3) -> (-13.5, -18.3)
  line L3 (-27.2, 18.3) -> (-27.2, -18.3)
  line L4 (-13.5, 18.3) -> (-27.2, 18.3)
  line L5 (-13.5, 19.3) -> (-13.5, 18.3)
  line L6 (-28.2, 19.3) -> (-13.5, 19.3)
  line L7 (-28.2, -19.3) -> (-28.2, 19.3)
  line L8 (-13.5, -19.3) -> (-28.2, -19.3)
extrude "Extrude1" new body sketch "SK_Retention_Strap_U" along normal blind 5
copy_paste "CopyPaste2"
place_component sketch "SK_PCB_Substrate"
work_plane "WorkPlane1" AlongDistance 177.85 ExtraOffset 0
sketch "SK_Connector_Plate_Blank" plane through (177.85, 0, 0) normal (1, 0, 0) x axis (0, 0, -1)
  line L1 (-14, 33) -> (-14, -33)
  line L2 (-38.5, 33) -> (-14, 33)
  line L3 (-38.5, -33) -> (-38.5, 33)
  line L4 (-14, -33) -> (-38.5, -33)
face "BaseFlange2" sketch "SK_Connector_Plate_Blank"
sketch "SK_Connector_Plate_Cutouts" plane through (177.85, 0, 0) normal (1, 0, 0) x axis (0, 0, -1)
  line L1 (-22, 5.5) -> (-22, -5.5)
  line L2 (-28, 5.5) -> (-22, 5.5)
  line L3 (-28, -5.5) -> (-28, 5.5)
  line L4 (-22, -5.5) -> (-28, -5.5)
  circle C1 centre (-18, -28.5) radius 1.1
  circle C2 centre (-34, -28.5) radius 1.1
  circle C3 centre (-18, 28.5) radius 1.1
  circle C4 centre (-34, 28.5) radius 1.1
  circle C5 centre (-25, -16) radius 4.5
  circle C6 centre (-25, 16) radius 4.5
  circle C7 centre (-25, -7) radius 1.1
  circle C8 centre (-25, 7) radius 1.1
extrude "Extrude1" cut sketch "SK_Connector_Plate_Cutouts" distance 2
sketch "SK_Conn_Flange" plane through (0, 0, 0) normal (0, 0, 1) x axis (1, 0, 0)
  circle C1 centre (0, 0) radius 6.25
extrude "Extrude1" new body sketch "SK_Conn_Flange" along a picked direction blind 1.5
work_plane "WorkPlane1" AlongDistance -2.6 ExtraOffset 0
sketch "SK_Conn_Rear_Body" plane through (0, 0, -2.6) normal (0, 0, 1) x axis (1, 0, 0)
  circle C1 centre (0, 0) radius 4.4
extrude "Extrude2" add sketch "SK_Conn_Rear_Body" along a picked direction blind 2.6
work_plane "WorkPlane2" AlongDistance 1.5 ExtraOffset 0
sketch "SK_Conn_Mating_Barrel" plane through (0, 0, 1.5) normal (0, 0, 1) x axis (1, 0, 0)
  circle C1 centre (0, 0) radius 4.5
  circle C2 centre (0, 0) radius 3.1
extrude "Extrude3" add sketch "SK_Conn_Mating_Barrel" along a picked direction blind 4.5
copy_paste "CopyPaste1"
place_component sketch "SK_PCB_Substrate"
work_plane "WorkPlane1" AlongDistance 20.5 ExtraOffset 0
sketch "SK_MicroD_Flange" plane through (0, 0, 20.5) normal (0, 0, 1) x axis (1, 0, 0)
  line L1 (179.35, -8.5) -> (177.85, -8.5)
  line L2 (179.35, 8.5) -> (179.35, -8.5)
  line L3 (177.85, 8.5) -> (179.35, 8.5)
  line L4 (177.85, -8.5) -> (177.85, 8.5)
extrude "Extrude1" new body sketch "SK_MicroD_Flange" along normal blind 9
work_plane "WorkPlane2" AlongDistance 22.1 ExtraOffset 0
sketch "SK_MicroD_Rear_Body" plane through (0, 0, 22.1) normal (0, 0, 1) x axis (1, 0, 0)
  line L1 (177.85, -5.4) -> (175.25, -5.4)
  line L2 (177.85, 5.4) -> (177.85, -5.4)
  line L3 (175.25, 5.4) -> (177.85, 5.4)
  line L4 (175.25, -5.4) -> (175.25, 5.4)
extrude "Extrude2" add sketch "SK_MicroD_Rear_Body" along normal blind 5.8
work_plane "WorkPlane3" AlongDistance 22.1 ExtraOffset 0
sketch "SK_MicroD_Shroud" plane through (0, 0, 22.1) normal (0, 0, 1) x axis (1, 0, 0)
  line L1 (183.05, -5.4) -> (179.35, -5.4)
  line L2 (183.05, 5.4) -> (183.05, -5.4)
  line L3 (179.35, 5.4) -> (183.05, 5.4)
  line L4 (179.35, -5.4) -> (179.35, 5.4)
extrude "Extrude3" add sketch "SK_MicroD_Shroud" along normal blind 5.8
work_plane "WorkPlane4" AlongDistance 23.1 ExtraOffset 0
sketch "SK_MicroD_Pin_Pocket" plane through (0, 0, 23.1) normal (0, 0, 1) x axis (1, 0, 0)
  line L1 (183.45, -4.4) -> (180.25, -4.4)
  line L2 (183.45, 4.4) -> (183.45, -4.4)
  line L3 (180.25, 4.4) -> (183.45, 4.4)
  line L4 (180.25, -4.4) -> (180.25, 4.4)
extrude "Extrude4" cut sketch "SK_MicroD_Pin_Pocket" along normal blind 3.8
work_plane "WorkPlane5" AlongDistance 177.85 ExtraOffset 0
sketch "SK_MicroD_Jackposts" plane through (177.85, 0, 0) normal (1, 0, 0) x axis (0, 0, -1)
  circle C1 centre (-25, -7) radius 1.1
  circle C2 centre (-25, 7) radius 1.1
extrude "Extrude5" cut sketch "SK_MicroD_Jackposts" distance 2.5
place_component sketch "SK_PCB_Substrate"
work_plane "WorkPlane1" AlongDistance 176.85 ExtraOffset 0
sketch "SK_Strain_Relief_Blank" plane through (176.85, 0, 0) normal (1, 0, 0) x axis (0, 0, -1)
  line L1 (-31.8, 32) -> (-31.8, -32)
  line L2 (-38.5, 32) -> (-31.8, 32)
  line L3 (-38.5, -32) -> (-38.5, 32)
  line L4 (-31.8, -32) -> (-38.5, -32)
face "BaseFlange2" sketch "SK_Strain_Relief_Blank"
face "EdgeFlange3" FlangeHeight 8 FlangeAngle 90
sketch "SK_Strain_Relief_Mount_Holes" plane through (176.85, 0, 0) normal (1, 0, 0) x axis (0, 0, -1)
  circle C1 centre (-34, -28.5) radius 1.1
  circle C2 centre (-34, 28.5) radius 1.1
extrude "Extrude1" cut sketch "SK_Strain_Relief_Mount_Holes" distance 2
work_plane "WorkPlane2" AlongDistance 38.5 ExtraOffset 0
sketch "SK_Strain_Relief_Tie_Slots" plane through (0, 0, 38.5) normal (0, 0, 1) x axis (1, 0, 0)
  line L1 (173.25, -14.25) -> (173.25, -17.75)
  line L2 (170.75, -17.75) -> (170.75, -14.25)
  line L3 (173.25, 1.75) -> (173.25, -1.75)
  line L4 (170.75, -1.75) -> (170.75, 1.75)
  line L5 (173.25, 17.75) -> (173.25, 14.25)
  line L6 (170.75, 14.25) -> (170.75, 17.75)
  arc A1 centre (172, -14.25) radius 1.25 clockwise from (170.75, -14.25) to (173.25, -14.25)
  arc A2 centre (172, -17.75) radius 1.25 clockwise from (173.25, -17.75) to (170.75, -17.75)
  arc A3 centre (172, 1.75) radius 1.25 clockwise from (170.75, 1.75) to (173.25, 1.75)
  arc A4 centre (172, -1.75) radius 1.25 clockwise from (173.25, -1.75) to (170.75, -1.75)
  arc A5 centre (172, 17.75) radius 1.25 clockwise from (170.75, 17.75) to (173.25, 17.75)
  arc A6 centre (172, 14.25) radius 1.25 clockwise from (173.25, 14.25) to (170.75, 14.25)
extrude "Extrude2" cut sketch "SK_Strain_Relief_Tie_Slots" distance 2
place_component sketch "SK_PCB_Substrate"
work_plane "WorkPlane1" AlongDistance 1 ExtraOffset 0
sketch "SK_Cable_Channel_Blank" plane through (0, 0, 1) normal (0, 0, 1) x axis (1, 0, 0)
  line L1 (166, 8.5) -> (98, 8.5)
  line L2 (166, 21.5) -> (166, 8.5)
  line L3 (98, 21.5) -> (166, 21.5)
  line L4 (98, 8.5) -> (98, 21.5)
face "BaseFlange1" sketch "SK_Cable_Channel_Blank"
face "EdgeFlange2" FlangeHeight 5 FlangeAngle 90
sketch "SK_Cable_Channel_Holes" plane through (0, 0, 1) normal (0, 0, 1) x axis (1, 0, 0)
  circle C1 centre (112, 12.5) radius 1.1
  circle C2 centre (152, 12.5) radius 1.1
extrude "Extrude1" cut sketch "SK_Cable_Channel_Holes" distance 2
sketch "SK_Cable_Clamp_Blank" plane through (0, 0, 0) normal (0, 0, 1) x axis (1, 0, 0)
  line L1 (3.5, -6.5) -> (-3.5, -6.5)
  line L2 (3.5, 4.5) -> (3.5, -6.5)
  line L3 (-3.5, 4.5) -> (3.5, 4.5)
  line L4 (-3.5, -6.5) -> (-3.5, 4.5)
face "BaseFlange1" sketch "SK_Cable_Clamp_Blank"
face "EdgeFlange2" FlangeHeight 5 FlangeAngle 90
face "EdgeFlange3" FlangeHeight 5 FlangeAngle 90
sketch "SK_Cable_Clamp_Hole" plane through (0, 0, 0) normal (0, 0, 1) x axis (1, 0, 0)
  circle C1 centre (0, -2.5) radius 1.1
extrude "Extrude1" cut sketch "SK_Cable_Clamp_Hole" distance 2
copy_paste "CopyPaste1"
copy_paste "CopyPaste2"
place_component sketch "SK_PCB_Substrate"
work_plane "WorkPlane1" AlongDistance 17.5 ExtraOffset 0
sketch "SK_PDB-07-703_Power_Harness_Visual_Path" plane through (0, 17.5, 0) normal (0, 1, 0) x axis (1, 0, 0)
  line L1 (171.2, -3.2) -> (48.5, -3.2)
  line L2 (175.2, -20.4) -> (175.2, -7.2)
  arc A1 centre (171.2, -7.2) radius 4 clockwise from (171.2, -3.2) to (175.2, -7.2)
work_plane "WorkPlane2" AlongDistance 48.5 ExtraOffset 0
sketch "SK_PDB-07-703_Power_Harness_Visual_Profile" plane through (48.5, 0, 0) normal (1, 0, 0) x axis (0, 0, -1)
  circle C1 centre (-3.2, 17.5) radius 1
sweep "Sweep1" sketch "SK_PDB-07-703_Power_Harness_Visual_Profile" TwistAngle 0 TaperAngle 0
place_component sketch "SK_PCB_Substrate"
work_plane "WorkPlane1" AlongDistance -13.5 ExtraOffset 0
sketch "SK_PDB-07-704_Signal_Harness_Visual_Path" plane through (0, -13.5, 0) normal (0, 1, 0) x axis (1, 0, 0)
  line L1 (171.2, -3) -> (104, -3)
  line L2 (175.2, -20.4) -> (175.2, -7)
  arc A1 centre (171.2, -7) radius 4 clockwise from (171.2, -3) to (175.2, -7)
work_plane "WorkPlane2" AlongDistance 104 ExtraOffset 0
sketch "SK_PDB-07-704_Signal_Harness_Visual_Profile" plane through (104, 0, 0) normal (1, 0, 0) x axis (0, 0, -1)
  circle C1 centre (-3, -13.5) radius 1
sweep "Sweep1" sketch "SK_PDB-07-704_Signal_Harness_Visual_Profile" TwistAngle 0 TaperAngle 0
sketch "SK_Fastener_Head" plane through (0, 0, 0) normal (0, 0, 1) x axis (1, 0, 0)
  circle C1 centre (0, 0) radius 2.25
extrude "Extrude1" new body sketch "SK_Fastener_Head" along a picked direction blind 1.2
sketch "SK_Fastener_Shank" plane through (0, 0, 0) normal (0, 0, 1) x axis (1, 0, 0)
  circle C1 centre (0, 0) radius 1.25
extrude "Extrude2" add sketch "SK_Fastener_Shank" along a picked direction blind -5
copy_paste "CopyPaste1"
copy_paste "CopyPaste2"
copy_paste "CopyPaste3"
copy_paste "CopyPaste4"
copy_paste "CopyPaste5"
copy_paste "CopyPaste6"
copy_paste "CopyPaste7"
copy_paste "CopyPaste8"
copy_paste "CopyPaste9"
copy_paste "CopyPaste10"
copy_paste "CopyPaste11"
copy_paste "CopyPaste12"
copy_paste "CopyPaste13"
copy_paste "CopyPaste14"
copy_paste "CopyPaste15"
copy_paste "CopyPaste16"
copy_paste "CopyPaste17"
copy_paste "CopyPaste18"
copy_paste "CopyPaste19"
copy_paste "CopyPaste20"
copy_paste "CopyPaste21"
copy_paste "CopyPaste22"
copy_paste "CopyPaste23"
copy_paste "CopyPaste24"
copy_paste "CopyPaste25"
copy_paste "CopyPaste26"
copy_paste "CopyPaste27"
copy_paste "CopyPaste28"
copy_paste "CopyPaste29"
copy_paste "CopyPaste30"
copy_paste "CopyPaste31"
place_component sketch "SK_Hardware_Ring"
sketch "SK_Hardware_Ring" plane through (0, 0, 0) normal (0, 0, 1) x axis (1, 0, 0)
  circle C1 centre (0, 0) radius 2.75
  circle C2 centre (0, 0) radius 1.35
extrude "Extrude1" new body sketch "SK_Hardware_Ring" along normal blind 0.5
copy_paste "CopyPaste32"
copy_paste "CopyPaste33"
copy_paste "CopyPaste34"
copy_paste "CopyPaste35"
copy_paste "CopyPaste36"
copy_paste "CopyPaste37"
copy_paste "CopyPaste38"
copy_paste "CopyPaste39"
copy_paste "CopyPaste40"
copy_paste "CopyPaste41"
copy_paste "CopyPaste42"
place_component sketch "SK_Hardware_Ring"
sketch "SK_Hardware_Ring" plane through (0, 0, 0) normal (0, 0, 1) x axis (1, 0, 0)
  circle C1 centre (0, 0) radius 2.5
  circle C2 centre (0, 0) radius 1.25
extrude "Extrude1" new body sketch "SK_Hardware_Ring" along a picked direction blind 2
copy_paste "CopyPaste43"
copy_paste "CopyPaste44"
copy_paste "CopyPaste45"
copy_paste "CopyPaste46"
copy_paste "CopyPaste47"
copy_paste "CopyPaste48"
copy_paste "CopyPaste49"
copy_paste "CopyPaste50"
copy_paste "CopyPaste51"
copy_paste "CopyPaste52"
copy_paste "CopyPaste53"
copy_paste "CopyPaste54"
copy_paste "CopyPaste55"
copy_paste "CopyPaste56"
copy_paste "CopyPaste57"
copy_paste "CopyPaste58"
copy_paste "CopyPaste59"
copy_paste "CopyPaste60"
copy_paste "CopyPaste61"
copy_paste "CopyPaste62"
copy_paste "CopyPaste63"
copy_paste "CopyPaste64"
copy_paste "CopyPaste65"
sketch "SK_Fastener_Head" plane through (0, 0, 0) normal (0, 0, 1) x axis (1, 0, 0)
  circle C1 centre (0, 0) radius 1.8
extrude "Extrude1" new body sketch "SK_Fastener_Head" along normal blind 0.9
sketch "SK_Fastener_Shank" plane through (0, 0, 0) normal (0, 0, 1) x axis (1, 0, 0)
  circle C1 centre (0, 0) radius 1
extrude "Extrude2" add sketch "SK_Fastener_Shank" against normal blind 4
copy_paste "CopyPaste66"
copy_paste "CopyPaste67"
copy_paste "CopyPaste68"
copy_paste "CopyPaste69"
copy_paste "CopyPaste70"
copy_paste "CopyPaste71"
copy_paste "CopyPaste72"
copy_paste "CopyPaste73"
copy_paste "CopyPaste74"
copy_paste "CopyPaste75"
copy_paste "CopyPaste76"
copy_paste "CopyPaste77"
copy_paste "CopyPaste78"
copy_paste "CopyPaste79"
copy_paste "CopyPaste80"
copy_paste "CopyPaste81"
copy_paste "CopyPaste82"
copy_paste "CopyPaste83"
copy_paste "CopyPaste84"
copy_paste "CopyPaste85"
copy_paste "CopyPaste86"
copy_paste "CopyPaste87"
copy_paste "CopyPaste88"
place_component sketch "SK_Hardware_Ring"
sketch "SK_Hardware_Ring" plane through (0, 0, 0) normal (0, 0, 1) x axis (1, 0, 0)
  circle C1 centre (0, 0) radius 2.25
  circle C2 centre (0, 0) radius 1.05
extrude "Extrude1" new body sketch "SK_Hardware_Ring" along normal blind 0.8
copy_paste "CopyPaste89"
copy_paste "CopyPaste90"
copy_paste "CopyPaste91"
copy_paste "CopyPaste92"
copy_paste "CopyPaste93"
copy_paste "CopyPaste94"
copy_paste "CopyPaste95"
sketch "SK_Fastener_Head" plane through (0, 0, 0) normal (0, 0, 1) x axis (1, 0, 0)
  circle C1 centre (0, 0) radius 1.8
extrude "Extrude1" new body sketch "SK_Fastener_Head" along normal blind 0.9
sketch "SK_Fastener_Shank" plane through (0, 0, 0) normal (0, 0, 1) x axis (1, 0, 0)
  circle C1 centre (0, 0) radius 1
extrude "Extrude2" add sketch "SK_Fastener_Shank" against normal blind 3
copy_paste "CopyPaste96"
copy_paste "CopyPaste97"
copy_paste "CopyPaste98"
copy_paste "CopyPaste99"
copy_paste "CopyPaste100"
copy_paste "CopyPaste101"
copy_paste "CopyPaste102"
sketch "SK_Fastener_Head" plane through (0, 0, 0) normal (0, 0, 1) x axis (1, 0, 0)
  circle C1 centre (0, 0) radius 1.8
extrude "Extrude1" new body sketch "SK_Fastener_Head" along normal blind 0.6
sketch "SK_Fastener_Shank" plane through (0, 0, 0) normal (0, 0, 1) x axis (1, 0, 0)
  circle C1 centre (0, 0) radius 1
extrude "Extrude2" add sketch "SK_Fastener_Shank" against normal blind 1.8
copy_paste "CopyPaste103"
copy_paste "CopyPaste104"
copy_paste "CopyPaste105"
copy_paste "CopyPaste106"
copy_paste "CopyPaste107"
copy_paste "CopyPaste108"
copy_paste "CopyPaste109"
copy_paste "CopyPaste110"
sketch "SK_Fastener_Head" plane through (0, 0, 0) normal (0, 0, 1) x axis (1, 0, 0)
  circle C1 centre (0, 0) radius 2.25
